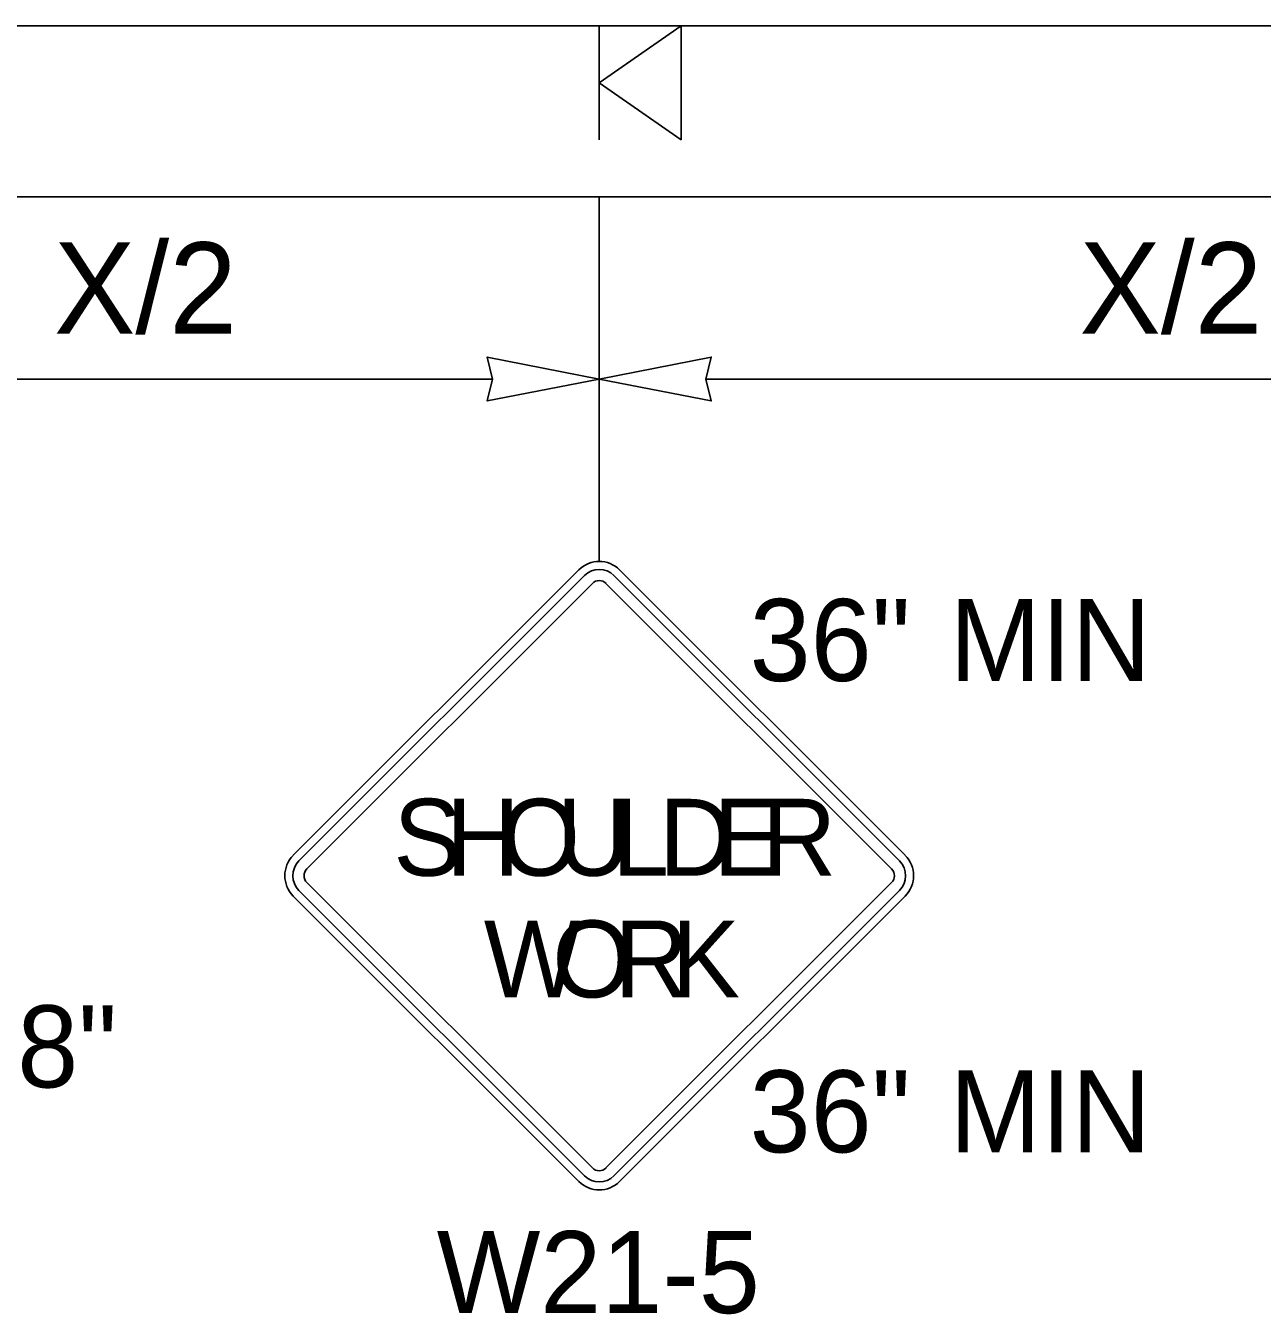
# Model space of a CAD drawing. Extents: x 99999.1 to 100055.7, y 99995 to 100010.7.
# Drawn here: x 100004.272 to 100005.357, y 100004.255 to 100005.386 of the extents above; entities that cross this region are included whole.
import ezdxf

# ---------------------------------------------------------------- set-up
doc = ezdxf.new("R2010")
doc.units = 0
for name, color, linetype in [('RD_ED_ShoulderPavedEdge', 7, 'Continuous'), ('TR_SN_ConstructionSigns', 7, 'Continuous'), ('TR_WZ_PortableSignMountBlk-Org', 7, 'Continuous'), ('TR_WZ_WorkZoneDetails', 7, 'Continuous'), ('TR_WZ_WorkZoneTextCurrent', 7, 'Continuous')]:
    doc.layers.add(name, color=color, linetype=linetype)

msp = doc.modelspace()

# ---------------------------------------------------------------- linework, layer by layer
at = {"layer": 'RD_ED_ShoulderPavedEdge'}
msp.add_line((100000.8283, 100005.2357), (100015.62, 100005.2357), dxfattribs=at)
at = {"layer": 'TR_SN_ConstructionSigns'}
for p, q in [((100004.7574, 100004.9083), (100004.5068, 100004.6577)), ((100004.7624, 100004.9033), (100004.5118, 100004.6528)), ((100005.0388, 100004.6528), (100004.7882, 100004.9033)), ((100005.0438, 100004.6577), (100004.7932, 100004.9083)), ((100004.5187, 100004.6458), (100004.7693, 100004.8964)), ((100004.7812, 100004.8964), (100005.0318, 100004.6458)), ((100004.7693, 100004.3833), (100004.5187, 100004.6339)), ((100005.0318, 100004.6339), (100004.7812, 100004.3833)), ((100004.5068, 100004.6219), (100004.7574, 100004.3714)), ((100004.5118, 100004.6269), (100004.7624, 100004.3763)), ((100004.7882, 100004.3763), (100005.0388, 100004.6269)), ((100004.7932, 100004.3714), (100005.0438, 100004.6219))]:
    msp.add_line(p, q, dxfattribs=at)
for centre, radius, start, end in [((100004.7753, 100004.8904), 0.0253, 45, 135), ((100004.7753, 100004.8904), 0.0183, 45, 135), ((100004.7753, 100004.8904), 0.00844, 45, 135), ((100004.5247, 100004.6398), 0.0253, 135, 225), ((100004.5247, 100004.6398), 0.0183, 135, 225), ((100005.0259, 100004.6398), 0.0183, 315, 45), ((100005.0259, 100004.6398), 0.0253, 315, 45), ((100004.5247, 100004.6398), 0.00844, 135, 225), ((100005.0259, 100004.6398), 0.00844, 315, 45), ((100004.7753, 100004.3893), 0.00844, 225, 315), ((100004.7753, 100004.3893), 0.0253, 225, 315), ((100004.7753, 100004.3893), 0.0183, 225, 315)]:
    msp.add_arc(centre, radius, start, end, dxfattribs=at)
at = {"layer": 'TR_WZ_PortableSignMountBlk-Org'}
msp.add_line((100004.7753, 100005.2858), (100004.7753, 100005.3858), dxfattribs=at)
msp.add_lwpolyline([(100004.7753, 100005.3357), (100004.8471, 100005.3858), (100004.8471, 100005.2858)], close=True, dxfattribs=at)
at = {"layer": 'TR_WZ_WorkZoneDetails'}
for p, q in [((100003.1753, 100005.3858), (100006.6368, 100005.3858)), ((100004.7753, 100005.236), (100004.7753, 100004.9157)), ((100004.6815, 100005.0757), (100004.069, 100005.0757)), ((100005.6815, 100005.0757), (100004.869, 100005.0757))]:
    msp.add_line(p, q, dxfattribs=at)
for points in [[(100004.7753, 100005.0757), (100004.677, 100005.095), (100004.6815, 100005.0757), (100004.677, 100005.0565)], [(100004.7753, 100005.0757), (100004.8736, 100005.095), (100004.869, 100005.0757), (100004.8736, 100005.0565)]]:
    msp.add_lwpolyline(points, close=True, dxfattribs=at)

# ---------------------------------------------------------------- texts
at = {"layer": 'TR_SN_ConstructionSigns'}
for s, p in [('36"', (100004.9073, 100004.8107)), ('MIN', (100005.0829, 100004.8107)), ('48"', (100004.211, 100004.454)), ('36"', (100004.9073, 100004.397)), ('MIN', (100005.0829, 100004.397)), ('W21-5', (100004.6327, 100004.2559))]:
    msp.add_text(s, height=0.072, rotation=360, dxfattribs=at).set_placement(p)
for s, p in [('S', (100004.5946, 100004.6398)), ('O', (100004.6883, 100004.6398)), ('H', (100004.6407, 100004.6398)), ('U', (100004.7379, 100004.6398)), ('L', (100004.7865, 100004.6398)), ('D', (100004.8278, 100004.6398)), ('E', (100004.8754, 100004.6398)), ('R', (100004.9182, 100004.6398)), ('W', (100004.674, 100004.533)), ('O', (100004.7341, 100004.533)), ('R', (100004.7885, 100004.533)), ('K', (100004.8387, 100004.533))]:
    msp.add_text(s, height=0.0675, dxfattribs=at).set_placement(p)
at = {"layer": 'TR_WZ_WorkZoneTextCurrent'}
for p in [(100004.2968, 100005.1157), (100005.1968, 100005.1157)]:
    msp.add_text('X/2', height=0.08, rotation=360, dxfattribs=at).set_placement(p)

doc.saveas('drawing.dxf')
